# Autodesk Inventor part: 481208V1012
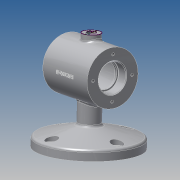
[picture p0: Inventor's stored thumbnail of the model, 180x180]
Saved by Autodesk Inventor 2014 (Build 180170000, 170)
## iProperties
Created: 2018-12
Part Number: 481208V1012
Material: 알루미늄 6061
Document SubType Name: Modeling
Designer: 601-24
Density: 2.71 g/cm^3
Appearance: 알루미늄 - 평지
Mass: 687.565 g
Surface Area: 554.846 cm^2
Volume: 253.714 cm^3
Author: 601-24
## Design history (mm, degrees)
sketch "스케치1"
  geometry: L1 (-35, 75)-(35, 75); L2 (-35, 92)-(-35, 105); L3 (-35, 105)-(35, 105); L4 (35, 105)-(35, 92); L5 (34, 91)-(23.3, 91); L6 (23, 90.7)-(23, 89); L7 (23, 89)-(20, 89); L8 (20, 89)-(20, 97); L9 (17, 100)-(-17, 100); L10 (-20, 97)-(-20, 89); L11 (-20, 89)-(-23, 89); L12 (-23, 89)-(-23, 90.7); L13 (-23.3, 91)-(-34, 91); L14 (-34, 91)-(-35, 92); L15 (34, 91)-(35, 92); A1 r 3 centre (17, 97) between (20, 97) and (17, 100); A2 r 3 centre (-17, 97) between (-17, 100) and (-20, 97); A3 r 0.3 centre (-23.3, 90.7) between (-23, 90.7) and (-23.3, 91); A4 r 0.3 centre (23.3, 90.7) between (23.3, 91) and (23, 90.7); 10 further points
  constraints: 30 end point, 20 point on line, 8 point on circle, 8 tangent, 7 perpendicular, 4 centre point, 4 parallel, 2 equal radius, 1 horizontal, 1 midpoint, 1 vertical alignment
  dimensions: "d0" = 70 distance of L1.start L1.end; "d1" = 75 distance from line of L1 point (0, 0); "d2" = 30 distance of L1.start L2.end; "d3" = 12 distance of point (35, 91) point (23, 91); "d4" = 40 distance of point (20, 100) point (-20, 100); "d5" = 12 distance of point (-23, 91) point (-35, 91); "d6" = 3 distance of L10.end L11.end; "d7" = 50 diameter of L9 L1; "d8" = 28 diameter of L11 L1; "d9" = 32 diameter of L13 L1; "d10" = 28 diameter of L7 L1; "d11" = 3 radius of A1; "d12" = 0.3 radius of A3; "d13" = 1 distance of L13.end point (-35, 91); "d14" = 1 distance of L2.start point (-35, 91) (= d13); "d15" = 1 distance of L5.start point (35, 91) (= d13); "d16" = 1 distance of L4.end point (35, 91) (= d15)
revolve "회전1" sketch "스케치1" stored, may be unused: angle "d17" = 90 deg
sketch "스케치2"
  geometry: C1 r 55 at (0, 0); C2 r 12 at (0, 0); C3 r 7 at (0, 44); C4 r 4.5 at (0, 44); C5 r 7 at (-44, 0); C6 r 4.5 at (-44, 0); C7 r 7 at (44, 0); C8 r 4.5 at (44, 0); C9 r 7 at (0, -44); C10 r 4.5 at (0, -44); A1 r 44 centre (0, 0) between (0, 44) and (-44, 0); 1 further point
  constraints: 11 centre point, 6 coincident, 5 point on circle
  dimensions: "d18" = 110 diameter of C1; "d19" = 24 diameter of C2; "d20" = 88 diameter of A1; "d21" = 14 diameter of C3; "d22" = 9 diameter of C4; "d23" = 14 diameter of C5; "d24" = 9 diameter of C6; "d25" = 14 diameter of C7; "d26" = 9 diameter of C8; "d27" = 14 diameter of C9; "d28" = 9 diameter of C10
sketch "스케치3"
  geometry: L1 (55, 10)-(-55, 10) reference; L2 (-35, 45)-(35, 45) reference; 1 further point
extrude "돌출3" join sketch "스케치2" stored distance "d33" = 10; taper "d34" = 0 deg
sketch "스케치5"
  geometry: L1 (0, 0)-(55, 0); L2 (55, 0)-(55, 8.698); L3 (52.776, 11.596)-(12, 22.522); L4 (12, 0)-(12, 45) reference; L5 (12, 22.522)-(12, 0); L6 (0, 0)-(0, 6.822); L7 (12, 0)-(55, 0); A1 r 3 centre (52, 8.698) between (55, 8.698) and (52.776, 11.596); 1 further point
  constraints: 12 end point, 3 point on line, 2 collinear, 2 point on circle, 2 tangent, 1 centre point, 1 horizontal, 1 parallel, 1 perpendicular
  dimensions: "d40" = 55 distance of L1.start L1.end; "d41" = 11 distance of L1.end point (55, 11); "d43" = 105 deg angle of L2 L3; "d44" = 3 radius of A1
revolve "회전3" sketch "스케치5" stored, may be unused: angle "d45" = 90 deg
fillet "모깎기1" dims "d46" = 3
fillet "모깎기2" dims "d47" = 3
sketch "스케치6" dims "d48" = 46
  geometry: C1 r 30 at (0, 0) reference; 3 further points
  constraints: 1 coincident, 1 vertical alignment, 2 other
hole "구멍1" sketch "스케치6" at (0, 23) diameter "d49" = 3.242; stored, may be unused: countersink angle "d53" = 90 deg, drill point angle "d55" = 118 deg; dims "d50" = 8, "d51" = 4, "d52" = 2, "d54" = 10
node "작업 평면1"
sketch "스케치7"
  geometry: C1 r 7 at (0, 44) reference; C2 r 7 at (44, 0) reference; C3 r 7 at (0, -44) reference; C4 r 7 at (-44, 0) reference; C5 r 7 at (0, 44); C6 r 7 at (-44, 0); C7 r 7 at (44, 0); C8 r 7 at (0, -44); 1 further point
  constraints: 4 centre point, 4 coincident, 4 concentric
extrude "돌출5" cut sketch "스케치7" distance "d60" = 20; taper "d61" = 0 deg
extrude "돌출6" cut sketch "스케치2" distance "d62" = 20; taper "d63" = 0 deg
node "작업 평면2"
sketch "스케치8"
  geometry: C1 r 10 at (0, 0); C2 r 5 at (0, 0); 1 further point
  constraints: 2 centre point, 2 coincident
  dimensions: "d65" = 20 diameter of C1; "d66" = 10 diameter of C2
extrude "돌출7" join sketch "스케치8" stored distance "d67" = 20; taper "d68" = 0 deg
extrude "돌출8" cut sketch "스케치8" stored distance "d69" = 20; taper "d70" = 0 deg
fillet "모깎기3" dims "d71" = 3
chamfer "모따기1" distance "d72" = 1; stored, may be unused: second distance "d73" = 2, angle "d74" = 45 deg
node "작업 평면3"
sketch "스케치9"
  geometry: L1 (-35, 105)-(35, 105) reference; L2 (-35, 45)-(-35, 105) reference; 2 further points
  constraints: 1 other
  dimensions: "d76" = 30 distance from line of L1 point (0, 75); "d77" = 35 distance from line of L2 point (0, 75)
feature "엠보싱1" sketch "스케치9" dims "d78" = 0.5, "d79" = 0
node "솔리드1"
pattern_circular "원형 패턴1" dims angle "d57" = 360 deg
mirror "대칭1"
other parameters: "d64" = 112
